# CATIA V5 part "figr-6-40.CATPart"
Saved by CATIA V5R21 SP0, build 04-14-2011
Part number: Part1
Bounding box of the stored display mesh (mm): x 0 to 45, y 0 to 76.536, z 0 to 111.001
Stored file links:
  D:\CATIA V5R21 E-RESOURCES\CATIA-V5R21\catia-v5r21-prt\c06-catia-v5r21-prt\c06-catia-v5r21-figr-6-40.CATPart
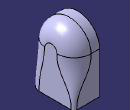
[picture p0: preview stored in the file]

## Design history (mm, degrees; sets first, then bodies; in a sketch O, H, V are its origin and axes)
Body1 (main body)
  Sketch1 on yz-plane, origin (0, 0, 0), H (0, 1, 0), V (0, 0, 1)
    line L1 (0, 0) -> (76.5361, 0)
    line L2 (76.5361, 0) -> (76.5361, 72.7325)
    line L3 (0, 0) -> (0, 72.7325)
    arc A1 centre (38.2681, 72.7325) radius 38.2681 from (76.5361, 72.7325) to (0, 72.7325) ccw
    horizontal: L1 H
    vertical: L2 V, L3 V
    tangency: A1 L3, A1 L2
  Pad1: profile Sketch1, direction (1, 0, 0), length 45
  Fillet1: on edge [face of Pad1 | face of Pad1] (x3)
